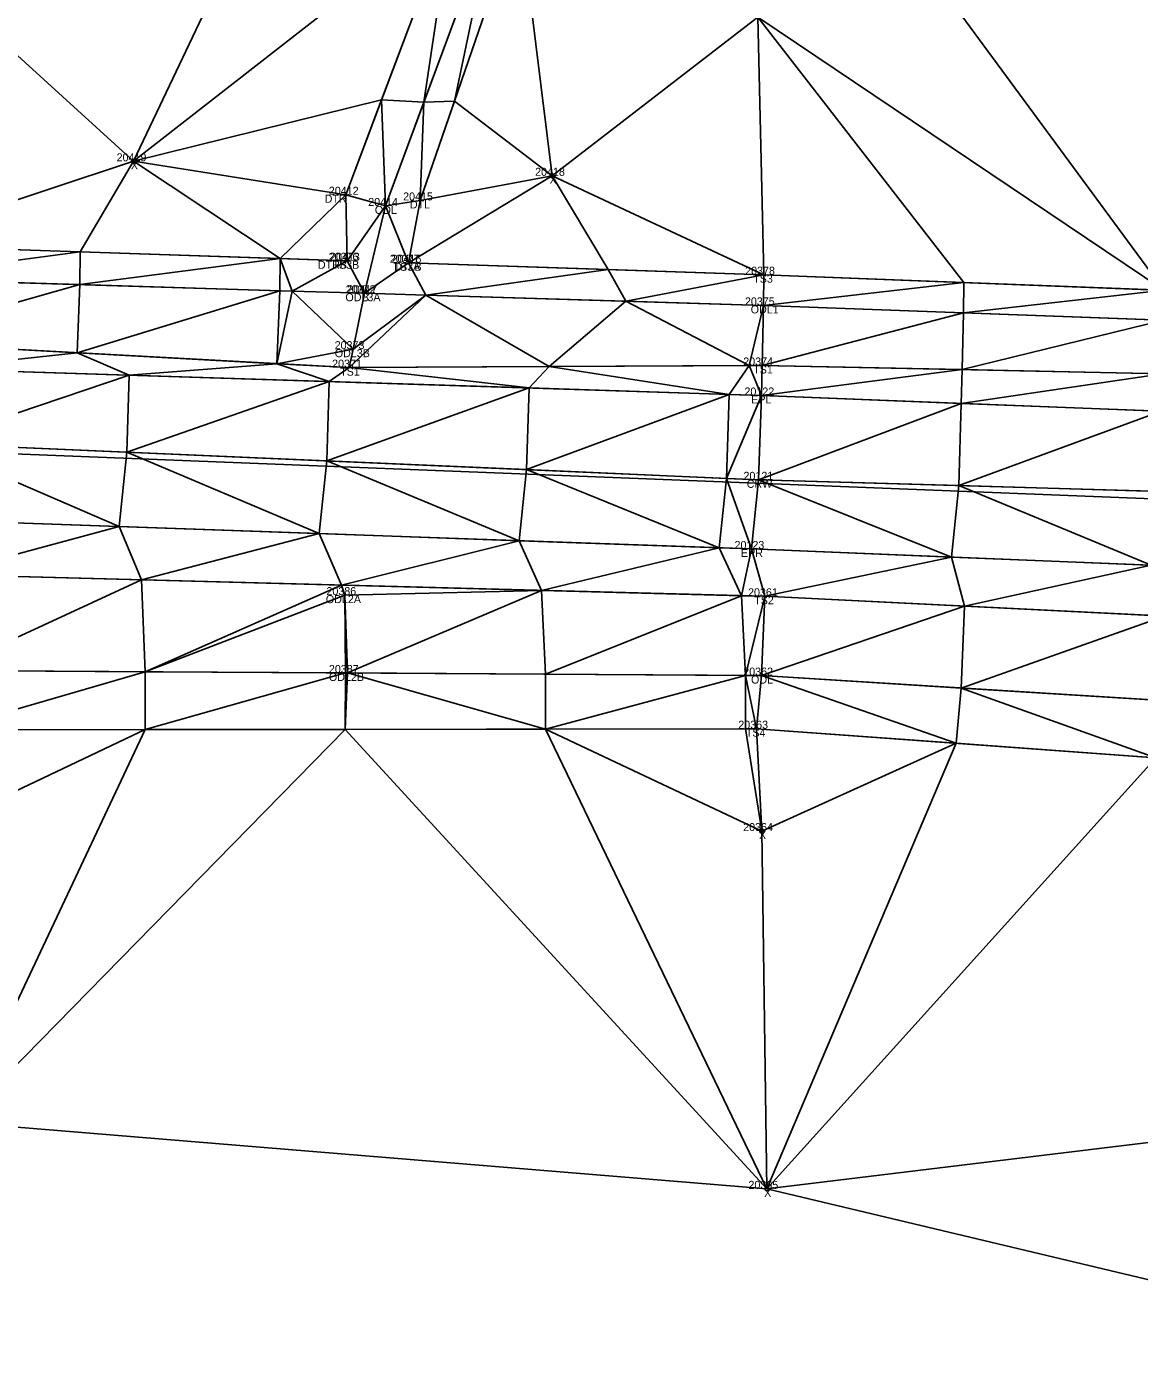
# Model space of a CAD drawing. Extents: x 1966740 to 1969291, y 1117379 to 1118460.
# Drawn here: x 1968331 to 1968470, y 1117808.5 to 1117976 of the extents above; entities that cross this region are included whole.
import ezdxf

# ---------------------------------------------------------------- set-up
doc = ezdxf.new("R2010")
doc.units = 0
for name, color, linetype in [('Level 1', 7, 'Continuous'), ('Level 10', 7, 'Continuous'), ('Level 3', 7, 'Continuous'), ('Level 30', 7, 'Continuous'), ('Level 35', 7, 'Continuous'), ('Level 50', 7, 'Continuous'), ('Level 52', 7, 'Continuous'), ('Level 53', 7, 'Continuous'), ('Level 56', 7, 'Continuous'), ('Level 6', 7, 'Continuous'), ('Level 60', 7, 'Continuous'), ('Level 61', 7, 'Continuous'), ('Level 62', 7, 'Continuous')]:
    doc.layers.add(name, color=color, linetype=linetype)

msp = doc.modelspace()

# ---------------------------------------------------------------- linework, layer by layer
at = {"layer": 'Level 1'}
msp.add_line((1968120.33, 1117930.94), (1969279.02, 1117884.95), dxfattribs=at)
at = {"layer": 'Level 10'}
for points in [[(1968464.83, 1118211.88), (1968447.38, 1118161.72), (1968428.66, 1118112.3), (1968410.49, 1118060.76), (1968392.92, 1118013.68), (1968370.86, 1117955.02), (1968371.01, 1117946.77)], [(1968473.95, 1118208.63), (1968457.08, 1118158.03), (1968439.1, 1118107.96), (1968419.78, 1118057.77), (1968400.7, 1118013.97), (1968380.14, 1117954.31), (1968378.68, 1117946.52)]]:
    msp.add_lwpolyline(points, dxfattribs=at)
at = {"layer": 'Level 3'}
for points in [[(1968106.63, 1117967.98), (1968158.56, 1117954.16), (1968212.75, 1117952.09), (1968371.01, 1117946.77)], [(1968378.68, 1117946.52), (1968423.07, 1117945.03), (1968532.27, 1117940.77)], [(1967874.77, 1117908.42), (1967879.51, 1117916.91), (1967881.27, 1117924.39), (1967885.24, 1117929.22), (1967913.7, 1117935.63), (1967966.11, 1117937.12), (1968012.39, 1117940.75), (1968059.42, 1117941.87), (1968105.44, 1117943.27), (1968158.32, 1117942.95), (1968212.48, 1117942.1), (1968371.25, 1117933.41), (1968422.85, 1117933.68), (1968531.49, 1117931.42)], [(1967878.98, 1117895.46), (1967875.66, 1117903.48), (1967919.49, 1117917.47), (1967966.4, 1117928.95), (1968012.66, 1117935.42), (1968058.94, 1117938.37), (1968105.99, 1117939.39), (1968158.7, 1117938.56), (1968212.05, 1117937.21), (1968318.79, 1117933.28), (1968422.76, 1117929.93), (1968530.54, 1117925.7)], [(1967878.98, 1117895.46), (1967922.07, 1117909.4), (1967968.89, 1117921.38), (1968013.49, 1117926.44), (1968059.29, 1117929.05), (1968105.63, 1117929.86), (1968159.12, 1117928.97), (1968212.65, 1117927.25), (1968318.5, 1117923.95), (1968422.42, 1117919.39), (1968529.36, 1117916.3)], [(1967878.98, 1117895.46), (1967883.11, 1117885.63), (1967924.99, 1117899.59), (1967970.68, 1117910.78), (1968014.42, 1117916.56), (1968059.13, 1117919.49), (1968105.39, 1117920.31), (1968159.16, 1117919.37), (1968212.5, 1117917.97), (1968317.55, 1117914.44), (1968421.52, 1117910.75), (1968527.82, 1117906.41)], [(1967884.1, 1117882.92), (1967891.06, 1117879.24), (1967898.84, 1117879.11), (1967924.17, 1117888.04), (1967954.33, 1117900.3), (1967970.81, 1117903.15), (1968012.93, 1117910.83), (1968059.62, 1117915.05), (1968105.25, 1117916.2), (1968157.57, 1117912.09), (1968210.74, 1117910.77), (1968320.32, 1117907.54), (1968423.18, 1117904.83), (1968528.99, 1117899.6)], [(1968058.02, 1117883.74), (1968104.17, 1117887.52), (1968156.67, 1117888.05), (1968209.1, 1117889.3), (1968320.79, 1117888.13), (1968422.17, 1117888.28), (1968528.68, 1117880.51)]]:
    msp.add_lwpolyline(points, dxfattribs=at)
at = {"layer": 'Level 30'}
for centre in [(1968344.33, 1117959.2), (1968396.63, 1117957.39), (1968422.81, 1117875.49), (1968423.45, 1117830.77)]:
    msp.add_circle(centre, 0.25, dxfattribs=at)
at = {"layer": 'Level 35'}
for points in [[(1968296.69, 1118002.64), (1968371.35, 1118016.1), (1968344.33, 1117959.2)], [(1968344.33, 1117959.2), (1968371.35, 1118016.1), (1968384.12, 1117990.28)], [(1968422.92, 1118011.27), (1968537.39, 1118012.98), (1968473.03, 1117943.08)], [(1968422.32, 1117977.2), (1968422.92, 1118011.27), (1968473.03, 1117943.08)], [(1968296.69, 1118002.64), (1968344.33, 1117959.2), (1968312.69, 1117948.73)], [(1968344.33, 1117959.2), (1968384.12, 1117990.28), (1968375.32, 1117966.88)], [(1968375.32, 1117966.88), (1968384.12, 1117990.28), (1968380.61, 1117966.58)], [(1968380.61, 1117966.58), (1968384.12, 1117990.28), (1968389.29, 1117990.02)], [(1968380.61, 1117966.58), (1968389.29, 1117990.02), (1968384.41, 1117966.7)], [(1968384.41, 1117966.7), (1968389.29, 1117990.02), (1968392.56, 1117990.33)], [(1968384.41, 1117966.7), (1968392.56, 1117990.33), (1968396.63, 1117957.39)], [(1968392.56, 1117990.33), (1968422.32, 1117977.2), (1968396.63, 1117957.39)], [(1968396.63, 1117957.39), (1968422.32, 1117977.2), (1968423.07, 1117945.03)], [(1968422.32, 1117977.2), (1968473.03, 1117943.08), (1968448.05, 1117944.05)], [(1968422.32, 1117977.2), (1968448.05, 1117944.05), (1968423.07, 1117945.03)], [(1968344.33, 1117959.2), (1968375.32, 1117966.88), (1968370.86, 1117955.02)], [(1968370.86, 1117955.02), (1968375.32, 1117966.88), (1968375.81, 1117953.62)], [(1968375.32, 1117966.88), (1968380.61, 1117966.58), (1968375.81, 1117953.62)], [(1968375.81, 1117953.62), (1968380.61, 1117966.58), (1968380.14, 1117954.31)], [(1968380.14, 1117954.31), (1968380.61, 1117966.58), (1968384.41, 1117966.7)], [(1968380.14, 1117954.31), (1968384.41, 1117966.7), (1968396.63, 1117957.39)], [(1968312.69, 1117948.73), (1968344.33, 1117959.2), (1968337.67, 1117947.89)], [(1968337.67, 1117947.89), (1968344.33, 1117959.2), (1968362.66, 1117947.06)], [(1968344.33, 1117959.2), (1968370.86, 1117955.02), (1968362.66, 1117947.06)], [(1968378.68, 1117946.52), (1968380.14, 1117954.31), (1968396.63, 1117957.39)], [(1968378.68, 1117946.52), (1968396.63, 1117957.39), (1968403.64, 1117945.68)], [(1968396.63, 1117957.39), (1968423.07, 1117945.03), (1968403.64, 1117945.68)], [(1968362.66, 1117947.06), (1968370.86, 1117955.02), (1968371.01, 1117946.77)], [(1968370.86, 1117955.02), (1968375.81, 1117953.62), (1968371.01, 1117946.77)], [(1968371.01, 1117946.77), (1968375.81, 1117953.62), (1968373.17, 1117942.71)], [(1968373.17, 1117942.71), (1968375.81, 1117953.62), (1968378.68, 1117946.52)], [(1968375.81, 1117953.62), (1968380.14, 1117954.31), (1968378.68, 1117946.52)], [(1968312.65, 1117944.55), (1968312.69, 1117948.73), (1968337.67, 1117947.89)], [(1968312.65, 1117944.55), (1968337.67, 1117947.89), (1968337.64, 1117943.79)], [(1968337.64, 1117943.79), (1968337.67, 1117947.89), (1968362.66, 1117947.06)], [(1968337.64, 1117943.79), (1968362.66, 1117947.06), (1968362.62, 1117943.03)], [(1968362.62, 1117943.03), (1968362.66, 1117947.06), (1968364.14, 1117942.98)], [(1968362.66, 1117947.06), (1968371.01, 1117946.77), (1968364.14, 1117942.98)], [(1968364.14, 1117942.98), (1968371.01, 1117946.77), (1968373.17, 1117942.71)], [(1968373.17, 1117942.71), (1968378.68, 1117946.52), (1968380.83, 1117942.48)], [(1968378.68, 1117946.52), (1968403.64, 1117945.68), (1968380.83, 1117942.48)], [(1968380.83, 1117942.48), (1968403.64, 1117945.68), (1968405.82, 1117941.71)], [(1968403.64, 1117945.68), (1968423.07, 1117945.03), (1968405.82, 1117941.71)], [(1968312.33, 1117936.64), (1968312.65, 1117944.55), (1968337.64, 1117943.79)], [(1968312.33, 1117936.64), (1968337.64, 1117943.79), (1968337.29, 1117935.27)], [(1968337.29, 1117935.27), (1968337.64, 1117943.79), (1968362.62, 1117943.03)], [(1968405.82, 1117941.71), (1968423.07, 1117945.03), (1968423.04, 1117941.19)], [(1968423.04, 1117941.19), (1968423.07, 1117945.03), (1968448.05, 1117944.05)], [(1968423.04, 1117941.19), (1968448.05, 1117944.05), (1968448.02, 1117940.27)], [(1968448.02, 1117940.27), (1968448.05, 1117944.05), (1968473.03, 1117943.08)], [(1968337.29, 1117935.27), (1968362.62, 1117943.03), (1968362.25, 1117933.9)], [(1968362.25, 1117933.9), (1968362.62, 1117943.03), (1968364.14, 1117942.98)], [(1968362.25, 1117933.9), (1968364.14, 1117942.98), (1968371.79, 1117935.72)], [(1968364.14, 1117942.98), (1968373.17, 1117942.71), (1968371.79, 1117935.72)], [(1968371.25, 1117933.41), (1968371.79, 1117935.72), (1968380.83, 1117942.48)], [(1968371.25, 1117933.41), (1968380.83, 1117942.48), (1968396.25, 1117933.54)], [(1968371.79, 1117935.72), (1968373.17, 1117942.71), (1968380.83, 1117942.48)], [(1968380.83, 1117942.48), (1968405.82, 1117941.71), (1968396.25, 1117933.54)], [(1968448.02, 1117940.27), (1968473.03, 1117943.08), (1968473, 1117939.35)], [(1968396.25, 1117933.54), (1968405.82, 1117941.71), (1968421.24, 1117933.67)], [(1968405.82, 1117941.71), (1968423.04, 1117941.19), (1968421.24, 1117933.67)], [(1968421.24, 1117933.67), (1968423.04, 1117941.19), (1968422.85, 1117933.68)], [(1968422.85, 1117933.68), (1968423.04, 1117941.19), (1968448.02, 1117940.27)], [(1968422.85, 1117933.68), (1968448.02, 1117940.27), (1968447.84, 1117933.16)], [(1968447.84, 1117933.16), (1968448.02, 1117940.27), (1968473, 1117939.35)], [(1968447.84, 1117933.16), (1968473, 1117939.35), (1968472.84, 1117932.64)], [(1968312.33, 1117936.64), (1968337.29, 1117935.27), (1968318.79, 1117933.28)], [(1968318.79, 1117933.28), (1968337.29, 1117935.27), (1968343.78, 1117932.48)], [(1968337.29, 1117935.27), (1968362.25, 1117933.9), (1968343.78, 1117932.48)], [(1968362.25, 1117933.9), (1968371.79, 1117935.72), (1968371.25, 1117933.41)], [(1968343.78, 1117932.48), (1968362.25, 1117933.9), (1968368.76, 1117931.67)], [(1968362.25, 1117933.9), (1968371.25, 1117933.41), (1968368.76, 1117931.67)], [(1968371.25, 1117933.41), (1968396.25, 1117933.54), (1968393.75, 1117930.87)], [(1968393.75, 1117930.87), (1968396.25, 1117933.54), (1968418.74, 1117930.06)], [(1968396.25, 1117933.54), (1968421.24, 1117933.67), (1968418.74, 1117930.06)], [(1968418.74, 1117930.06), (1968421.24, 1117933.67), (1968422.76, 1117929.93)], [(1968421.24, 1117933.67), (1968422.85, 1117933.68), (1968422.76, 1117929.93)], [(1968422.76, 1117929.93), (1968422.85, 1117933.68), (1968447.84, 1117933.16)], [(1968318.5, 1117923.95), (1968318.79, 1117933.28), (1968343.78, 1117932.48)], [(1968318.5, 1117923.95), (1968343.78, 1117932.48), (1968343.48, 1117922.85)], [(1968343.48, 1117922.85), (1968343.78, 1117932.48), (1968368.76, 1117931.67)], [(1968368.76, 1117931.67), (1968371.25, 1117933.41), (1968393.75, 1117930.87)], [(1968422.76, 1117929.93), (1968447.84, 1117933.16), (1968447.74, 1117928.95)], [(1968447.74, 1117928.95), (1968447.84, 1117933.16), (1968472.84, 1117932.64)], [(1968447.74, 1117928.95), (1968472.84, 1117932.64), (1968472.72, 1117927.97)], [(1968343.48, 1117922.85), (1968368.76, 1117931.67), (1968368.46, 1117921.76)], [(1968368.46, 1117921.76), (1968368.76, 1117931.67), (1968393.75, 1117930.87)], [(1968368.46, 1117921.76), (1968393.75, 1117930.87), (1968393.43, 1117920.66)], [(1968393.43, 1117920.66), (1968393.75, 1117930.87), (1968418.74, 1117930.06)], [(1968393.43, 1117920.66), (1968418.74, 1117930.06), (1968418.41, 1117919.57)], [(1968418.41, 1117919.57), (1968418.74, 1117930.06), (1968422.76, 1117929.93)], [(1968418.41, 1117919.57), (1968422.76, 1117929.93), (1968422.42, 1117919.39)], [(1968422.42, 1117919.39), (1968422.76, 1117929.93), (1968447.74, 1117928.95)], [(1968422.42, 1117919.39), (1968447.74, 1117928.95), (1968447.41, 1117918.67)], [(1968447.41, 1117918.67), (1968447.74, 1117928.95), (1968472.72, 1117927.97)], [(1968447.41, 1117918.67), (1968472.72, 1117927.97), (1968472.4, 1117917.95)], [(1968317.55, 1117914.44), (1968318.5, 1117923.95), (1968342.53, 1117913.55)], [(1968318.5, 1117923.95), (1968343.48, 1117922.85), (1968342.53, 1117913.55)], [(1968342.53, 1117913.55), (1968343.48, 1117922.85), (1968367.52, 1117912.67)], [(1968343.48, 1117922.85), (1968368.46, 1117921.76), (1968367.52, 1117912.67)], [(1968367.52, 1117912.67), (1968368.46, 1117921.76), (1968392.5, 1117911.78)], [(1968368.46, 1117921.76), (1968393.43, 1117920.66), (1968392.5, 1117911.78)], [(1968392.5, 1117911.78), (1968393.43, 1117920.66), (1968417.48, 1117910.9)], [(1968393.43, 1117920.66), (1968418.41, 1117919.57), (1968417.48, 1117910.9)], [(1968417.48, 1117910.9), (1968418.41, 1117919.57), (1968421.52, 1117910.75)], [(1968418.41, 1117919.57), (1968422.42, 1117919.39), (1968421.52, 1117910.75)], [(1968421.52, 1117910.75), (1968422.42, 1117919.39), (1968446.5, 1117909.73)], [(1968422.42, 1117919.39), (1968447.41, 1117918.67), (1968446.5, 1117909.73)], [(1968446.5, 1117909.73), (1968447.41, 1117918.67), (1968471.47, 1117908.71)], [(1968447.41, 1117918.67), (1968472.4, 1117917.95), (1968471.47, 1117908.71)], [(1968317.55, 1117914.44), (1968342.53, 1117913.55), (1968320.32, 1117907.54)], [(1968320.32, 1117907.54), (1968342.53, 1117913.55), (1968345.31, 1117906.88)], [(1968342.53, 1117913.55), (1968367.52, 1117912.67), (1968345.31, 1117906.88)], [(1968345.31, 1117906.88), (1968367.52, 1117912.67), (1968370.31, 1117906.22)], [(1968367.52, 1117912.67), (1968392.5, 1117911.78), (1968370.31, 1117906.22)], [(1968370.31, 1117906.22), (1968392.5, 1117911.78), (1968395.3, 1117905.56)], [(1968392.5, 1117911.78), (1968417.48, 1117910.9), (1968395.3, 1117905.56)], [(1968395.3, 1117905.56), (1968417.48, 1117910.9), (1968420.29, 1117904.9)], [(1968417.48, 1117910.9), (1968421.52, 1117910.75), (1968420.29, 1117904.9)], [(1968420.29, 1117904.9), (1968421.52, 1117910.75), (1968423.18, 1117904.83)], [(1968421.52, 1117910.75), (1968446.5, 1117909.73), (1968423.18, 1117904.83)], [(1968423.18, 1117904.83), (1968446.5, 1117909.73), (1968448.15, 1117903.59)], [(1968446.5, 1117909.73), (1968471.47, 1117908.71), (1968448.15, 1117903.59)], [(1968448.15, 1117903.59), (1968471.47, 1117908.71), (1968473.12, 1117902.36)], [(1968320.32, 1117907.54), (1968345.31, 1117906.88), (1968320.81, 1117895.57)], [(1968320.81, 1117895.57), (1968345.31, 1117906.88), (1968345.8, 1117895.41)], [(1968345.31, 1117906.88), (1968370.31, 1117906.22), (1968345.8, 1117895.41)], [(1968345.8, 1117895.41), (1968370.31, 1117906.22), (1968370.73, 1117904.98)], [(1968345.8, 1117895.41), (1968370.73, 1117904.98), (1968370.8, 1117895.25)], [(1968370.31, 1117906.22), (1968395.3, 1117905.56), (1968370.73, 1117904.98)], [(1968370.73, 1117904.98), (1968395.3, 1117905.56), (1968371.06, 1117895.25)], [(1968370.73, 1117904.98), (1968371.06, 1117895.25), (1968370.8, 1117895.25)], [(1968371.06, 1117895.25), (1968395.3, 1117905.56), (1968395.8, 1117895.09)], [(1968395.3, 1117905.56), (1968420.29, 1117904.9), (1968395.8, 1117895.09)], [(1968395.8, 1117895.09), (1968420.29, 1117904.9), (1968420.8, 1117894.93)], [(1968420.29, 1117904.9), (1968423.18, 1117904.83), (1968420.8, 1117894.93)], [(1968420.8, 1117894.93), (1968423.18, 1117904.83), (1968422.79, 1117894.92)], [(1968422.79, 1117894.92), (1968423.18, 1117904.83), (1968448.15, 1117903.59)], [(1968422.79, 1117894.92), (1968448.15, 1117903.59), (1968447.74, 1117893.37)], [(1968447.74, 1117893.37), (1968448.15, 1117903.59), (1968473.12, 1117902.36)], [(1968447.74, 1117893.37), (1968473.12, 1117902.36), (1968472.69, 1117891.82)], [(1968320.79, 1117888.13), (1968320.81, 1117895.57), (1968345.8, 1117895.41)], [(1968320.79, 1117888.13), (1968345.8, 1117895.41), (1968345.79, 1117888.17)], [(1968345.79, 1117888.17), (1968345.8, 1117895.41), (1968370.8, 1117895.25)], [(1968345.79, 1117888.17), (1968370.8, 1117895.25), (1968370.79, 1117888.2)], [(1968370.79, 1117888.2), (1968370.8, 1117895.25), (1968371.06, 1117895.25)], [(1968370.79, 1117888.2), (1968371.06, 1117895.25), (1968395.79, 1117888.24)], [(1968371.06, 1117895.25), (1968395.8, 1117895.09), (1968395.79, 1117888.24)], [(1968395.79, 1117888.24), (1968395.8, 1117895.09), (1968420.8, 1117894.93)], [(1968395.79, 1117888.24), (1968420.8, 1117894.93), (1968420.79, 1117888.27)], [(1968420.79, 1117888.27), (1968420.8, 1117894.93), (1968422.17, 1117888.28)], [(1968420.8, 1117894.93), (1968422.79, 1117894.92), (1968422.17, 1117888.28)], [(1968422.17, 1117888.28), (1968422.79, 1117894.92), (1968447.11, 1117886.46)], [(1968422.79, 1117894.92), (1968447.74, 1117893.37), (1968447.11, 1117886.46)], [(1968447.11, 1117886.46), (1968447.74, 1117893.37), (1968472.04, 1117884.64)], [(1968447.74, 1117893.37), (1968472.69, 1117891.82), (1968472.04, 1117884.64)], [(1968370.79, 1117888.2), (1968395.79, 1117888.24), (1968423.45, 1117830.77)], [(1968395.79, 1117888.24), (1968420.79, 1117888.27), (1968422.81, 1117875.49)], [(1968395.79, 1117888.24), (1968422.81, 1117875.49), (1968423.45, 1117830.77)], [(1968420.79, 1117888.27), (1968422.17, 1117888.28), (1968422.81, 1117875.49)], [(1968422.17, 1117888.28), (1968447.11, 1117886.46), (1968422.81, 1117875.49)], [(1968320.08, 1117875.98), (1968320.79, 1117888.13), (1968345.79, 1117888.17)], [(1968320.08, 1117875.98), (1968345.79, 1117888.17), (1968322.64, 1117839.05)], [(1968322.64, 1117839.05), (1968345.79, 1117888.17), (1968370.79, 1117888.2)], [(1968322.64, 1117839.05), (1968370.79, 1117888.2), (1968423.45, 1117830.77)], [(1968422.81, 1117875.49), (1968447.11, 1117886.46), (1968423.45, 1117830.77)], [(1968423.45, 1117830.77), (1968447.11, 1117886.46), (1968472.04, 1117884.64)], [(1968423.45, 1117830.77), (1968472.04, 1117884.64), (1968520.9, 1117842.62)], [(1968423.45, 1117830.77), (1968520.9, 1117842.62), (1968517.02, 1117808.48)]]:
    msp.add_lwpolyline(points, close=True, dxfattribs=at)
at = {"layer": 'Level 50'}
for centre in [(1968370.86, 1117955.02), (1968375.81, 1117953.62), (1968380.14, 1117954.31), (1968371.01, 1117946.77), (1968371.01, 1117946.77), (1968378.68, 1117946.52), (1968378.68, 1117946.52), (1968423.07, 1117945.03), (1968373.17, 1117942.71), (1968373.17, 1117942.71), (1968423.04, 1117941.19), (1968371.79, 1117935.72), (1968422.85, 1117933.68), (1968371.25, 1117933.41), (1968422.76, 1117929.93), (1968422.42, 1117919.39), (1968421.52, 1117910.75), (1968370.73, 1117904.98), (1968423.18, 1117904.83), (1968371.06, 1117895.25), (1968422.79, 1117894.92), (1968422.17, 1117888.28)]:
    msp.add_circle(centre, 0.001, dxfattribs=at)
at = {"layer": 'Level 6'}
for p, q in [((1968373.17, 1117942.71), (1968371.79, 1117935.72)), ((1968370.73, 1117904.98), (1968371.06, 1117895.25))]:
    msp.add_line(p, q, dxfattribs=at)
for points in [[(1968468.44, 1118210.37), (1968452.83, 1118159.99), (1968434.15, 1118109.1), (1968414.75, 1118059.53), (1968397.98, 1118013.47), (1968375.81, 1117953.62), (1968373.17, 1117942.71)], [(1968105.42, 1117949), (1968158.12, 1117948.98), (1968212.69, 1117947.6), (1968364.14, 1117942.98)], [(1968380.83, 1117942.48), (1968423.04, 1117941.19), (1968531.76, 1117937.18)], [(1967868.28, 1117817.14), (1967892.54, 1117814.5), (1967928.24, 1117834.22), (1967973.92, 1117854.29), (1967982.67, 1117861.15), (1968021.78, 1117883.3), (1968056.97, 1117897.44), (1968105.42, 1117898.77), (1968155.9, 1117899.84), (1968209.66, 1117898.76), (1968320.81, 1117895.57), (1968422.79, 1117894.92), (1968528.55, 1117888.35)]]:
    msp.add_lwpolyline(points, dxfattribs=at)

# ---------------------------------------------------------------- texts
at = {"layer": 'Level 52'}
for s, p in [('20419', (1968342.22, 1117959.2)), ('20418', (1968394.5, 1117957.39)), ('ODL3A', (1968370.8, 1117941.71)), ('ODL3B', (1968369.47, 1117934.72)), ('20364', (1968420.49, 1117875.49)), ('20365', (1968421.15, 1117830.77))]:
    msp.add_text(s, height=1, dxfattribs=at).set_placement(p)
at = {"layer": 'Level 53'}
for s, p in [('20376', (1968368.7, 1117946.77)), ('20377', (1968376.35, 1117946.52)), ('TS3B', (1968369.18, 1117945.77)), ('TS3A', (1968376.8, 1117945.52)), ('20378', (1968420.74, 1117945.03)), ('20372', (1968370.84, 1117942.71)), ('TS3', (1968421.74, 1117944.03)), ('20375', (1968420.71, 1117941.19)), ('ODL1', (1968421.43, 1117940.19)), ('20373', (1968369.46, 1117935.72)), ('20371', (1968369.14, 1117933.41)), ('20374', (1968420.5, 1117933.68)), ('TS1', (1968421.74, 1117932.68)), ('TS1', (1968370.14, 1117932.41)), ('20122', (1968420.65, 1117929.93)), ('EPL', (1968421.5, 1117928.93)), ('20121', (1968420.53, 1117919.39)), ('CRW', (1968420.93, 1117918.39)), ('20123', (1968419.41, 1117910.75)), ('EPR', (1968420.21, 1117909.75)), ('ODL2A', (1968368.36, 1117903.98)), ('20386', (1968368.43, 1117904.98)), ('20361', (1968421.1, 1117904.83)), ('TS2', (1968421.86, 1117903.83)), ('20387', (1968368.74, 1117895.25)), ('ODL2B', (1968368.74, 1117894.25)), ('20363', (1968419.88, 1117888.28)), ('TS4', (1968420.82, 1117887.28))]:
    msp.add_text(s, height=1, dxfattribs=at).set_placement(p)
at = {"layer": 'Level 56'}
for s, p in [('20414', (1968373.65, 1117953.62)), ('ODL', (1968374.48, 1117952.62)), ('20417', (1968371.04, 1117942.71)), ('B', (1968372.84, 1117941.71)), ('20362', (1968420.5, 1117894.92)), ('ODL', (1968421.47, 1117893.92))]:
    msp.add_text(s, height=1, dxfattribs=at).set_placement(p)
at = {"layer": 'Level 60'}
for s, p in [('DTR', (1968368.21, 1117954.02)), ('DTL', (1968378.86, 1117953.31)), ('DTRB', (1968367.36, 1117945.77)), ('DTLB', (1968376.9, 1117945.52))]:
    msp.add_text(s, height=1, dxfattribs=at).set_placement(p)
at = {"layer": 'Level 61'}
for s, p in [('20412', (1968368.73, 1117955.02)), ('20415', (1968378.01, 1117954.31)), ('20413', (1968368.88, 1117946.77)), ('20416', (1968376.57, 1117946.52))]:
    msp.add_text(s, height=1, dxfattribs=at).set_placement(p)
at = {"layer": 'Level 62'}
for p in [(1968344, 1117958.2), (1968396.3, 1117956.39), (1968422.47, 1117874.49), (1968423.11, 1117829.77)]:
    msp.add_text('X', height=1, dxfattribs=at).set_placement(p)

doc.saveas('drawing.dxf')
